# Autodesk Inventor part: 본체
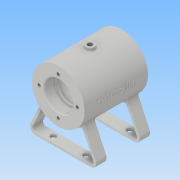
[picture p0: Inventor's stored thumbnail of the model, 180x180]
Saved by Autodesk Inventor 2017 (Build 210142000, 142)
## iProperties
Part Number: 본체
Material: 일반
Document SubType Name: Modeling
Designer: Administrator
Density: 1 g/cm^3
Appearance: 기본값
Author: Administrator
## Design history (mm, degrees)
sketch "스케치1"
  geometry: C1 r 29 at (0, 0); 1 further point
  constraints: 1 centre point, 1 coincident
  dimensions: "d0" = 58 diameter of C1
extrude "돌출1" new body sketch "스케치1" stored distance "d1" = 70; taper "d2" = 0 deg
sketch "스케치2"
  geometry: C1 r 16 at (0, 0); 1 further point
  constraints: 1 centre point, 1 coincident
  dimensions: "d3" = 32 diameter of C1
extrude "돌출2" cut sketch "스케치2" distance "d4" = 12; taper "d5" = 0 deg
sketch "스케치3"
  geometry: C1 r 14 at (0, 0); 1 further point
  constraints: 1 centre point, 1 coincident
  dimensions: "d6" = 28 diameter of C1
extrude "돌출3" cut sketch "스케치3" distance "d7" = 2; taper "d8" = 0 deg
sketch "스케치4"
  geometry: C1 r 21 at (0, 0); 1 further point
  constraints: 1 centre point, 1 coincident
  dimensions: "d9" = 42 diameter of C1
extrude "돌출4" cut sketch "스케치4" stored distance "d10" = 42; taper "d11" = 0 deg
node "작업 평면1"
sketch "스케치5"
  geometry: L1 (-40, -55)-(40, -55); L2 (40, -55)-(22.743, -17.993); L3 (-40, -55)-(-22.743, -17.993); L4 (0, -55)-(0, -29); C1 r 16 at (0, 0) reference; A1 r 29 centre (0, 0) between (22.743, -17.993) and (-22.743, -17.993) reference; A2 r 29 centre (0, 0) between (-22.743, -17.993) and (22.743, -17.993); A3 r 29 centre (0, 0) between (22.743, -17.993) and (0.836, 28.988); A4 r 29 centre (0, 0) between (0.836, 28.988) and (-22.743, -17.993); 1 further point
  constraints: 10 point on circle, 8 end point, 3 centre point, 1 coincident, 1 horizontal, 1 midpoint, 1 point on line, 1 vertical, 1 vertical alignment
  dimensions: "d13" = 80 distance of L1.start L1.end; "d14" = 55 distance from line of point (0, 0) L1; "d15" = 65 deg angle of L1 L2; "d16" = 65 deg angle of L1 L3
extrude "돌출5" join sketch "스케치5" distance "d18" = 12; taper "d19" = 0 deg
sketch "스케치6"
  geometry: L1 (-40, -55)-(-22.743, -17.993) reference; L2 (22.743, -17.993)-(40, -55) reference; L3 (40, -55)-(-40, -55) reference; L4 (-35.291, -52)-(35.291, -52); L5 (35.291, -52)-(20.574, -20.438); L6 (-35.291, -52)-(-20.574, -20.438); L7 (0, -52)-(0, -29); C1 r 16 at (0, 0) reference; A1 r 29 centre (0, 0) between (-22.743, -17.993) and (22.743, -17.993) reference; A2 r 29 centre (0, 0) between (22.743, -17.993) and (-22.743, -17.993) reference; A3 r 29 centre (0, 0) between (-22.743, -17.993) and (22.743, -17.993) reference; A4 r 29 centre (0, 0) between (22.743, -17.993) and (-20.574, -20.438); A5 r 29 centre (0, 0) between (20.574, -20.438) and (22.743, -17.993); A6 r 29 centre (0, 0) between (-20.574, -20.438) and (20.574, -20.438); 1 further point
  constraints: 13 point on circle, 9 end point, 3 centre point, 3 parallel, 1 coincident, 1 horizontal, 1 midpoint
  dimensions: "d21" = 3 distance between parallel lines of L1 L6; "d22" = 3 distance between parallel lines of L3 L4; "d23" = 3 distance between parallel lines of L2 L5
extrude "돌출6" cut sketch "스케치6" distance "d24" = 12; taper "d25" = 0 deg
node "작업 평면2"
sketch "스케치7"
  geometry: C1 r 5 at (0, 0); 1 further point
  constraints: 1 centre point, 1 coincident
  dimensions: "d27" = 10 diameter of C1
extrude "돌출7" join sketch "스케치7" stored distance "d28" = 12; taper "d29" = 0 deg
sketch "스케치8"
  geometry: 2 further points
  constraints: 1 coincident
hole "구멍1" sketch "스케치8" at (0, 0) diameter "d30" = 5.188; stored, may be unused: countersink angle "d34" = 90 deg, drill point angle "d36" = 118 deg; dims "d31" = 6, "d32" = 4, "d33" = 2, "d35" = 8
sketch "스케치9"
  geometry: C1 r 2.594 at (0, 0) reference; C2 r 5 at (0, 0) reference; C3 r 1.5 at (0, 0); 1 further point
  constraints: 1 centre point, 1 coincident
  dimensions: "d37" = 3 diameter of C3
extrude "돌출8" cut sketch "스케치9" distance "d38" = 20.75; taper "d39" = 0 deg
node "작업 평면4"
  node "작업 평면3"
sketch "스케치10"
  geometry: C1 r 6 at (0, 0); 1 further point
  constraints: 1 centre point, 1 coincident
  dimensions: "d42" = 12 diameter of C1
extrude "돌출9" join sketch "스케치10" stored distance "d43" = 20.75; taper "d44" = 0 deg
sketch "스케치11"
  geometry: 2 further points
  constraints: 1 coincident
hole "구멍2" sketch "스케치11" at (0, 0) diameter "d45" = 5.188; stored, may be unused: countersink angle "d49" = 90 deg, drill point angle "d51" = 118 deg; dims "d46" = 12, "d47" = 4, "d48" = 2, "d50" = 23
sketch "스케치12" dims "d52" = 42
  geometry: 3 further points
  constraints: 2 vertical alignment, 1 coincident, 2 other
hole "구멍3" sketch "스케치12" at (0, 21) diameter "d53" = 3.242; stored, may be unused: countersink angle "d57" = 90 deg, drill point angle "d59" = 118 deg; dims "d54" = 8, "d55" = 4, "d56" = 2, "d58" = 10
sketch "스케치13"
  geometry: L1 (0, -48)-(80, -48) reference; L2 (80, -48)-(80, -60) reference; L3 (80, -60)-(0, -60) reference; L4 (0, -60)-(0, -48) reference; L5 (0, 0)-(80, 0) reference; L6 (80, 0)-(80, -12) reference; L7 (80, -12)-(0, -12) reference; L8 (0, -12)-(0, 0) reference; L9 (41.621, -5)-(41.621, 5) reference; L10 (41.621, 0)-(41.621, -60); L11 (41.621, -65)-(41.621, -55) reference; C1 r 3 at (59.621, -6); C2 r 3 at (23.621, -6); C3 r 3 at (59.621, -54); C4 r 3 at (23.621, -54); 1 further point
  constraints: 4 centre point, 2 end point, 2 horizontal alignment, 2 midpoint, 2 vertical alignment
  dimensions: "d63" = 6 diameter of C1; "d64" = 6 diameter of C2; "d65" = 6 distance from line of L5 C1.centre; "d66" = 6 diameter of C3; "d67" = 6 diameter of C4; "d68" = 48 distance of C1.centre C3.centre; "d69" = 36 distance of C1.centre C2.centre; "d70" = 18 horizontal distance of L9.start C2.centre
extrude "돌출10" cut sketch "스케치13" distance "d71" = 3; taper "d72" = 0 deg
chamfer "모따기1" distance "d73" = 1; stored, may be unused: second distance "d74" = 2, angle "d75" = 45 deg
fillet "모깎기1" dims "d76" = 1, "d77" = 0.3, "d78" = 6
fillet "모깎기2" dims "d79" = 0.5
fillet "모깎기3" dims "d80" = 3
fillet "모깎기4" dims "d81" = 0.5
fillet "모깎기5" dims "d82" = 3
node "작업 평면5"
sketch "스케치14"
  geometry: L1 (29, -35)-(29, 35) reference; L2 (29, 35)-(-29, 35) reference; 2 further points
  constraints: 1 other
  dimensions: "d84" = 29 distance from line of point (0, 0) L1; "d85" = 35 distance from line of L2 point (0, 0)
feature "엠보싱1" sketch "스케치14" dims "d86" = 0.5, "d87" = 0
node "솔리드1"
mirror "미러1"
mirror "미러2"
pattern_circular "원형 패턴1" dims angle "d61" = 360 deg
mirror "미러3"
node "절단 모서리 투영1"
node "절단 모서리 투영2"
node "절단 모서리 투영3"
node "절단 모서리 투영4"
other parameters: "d12" = -5, "d26" = 32, "d40" = -20 deg, "d41" = -32, "d83" = 46.75
